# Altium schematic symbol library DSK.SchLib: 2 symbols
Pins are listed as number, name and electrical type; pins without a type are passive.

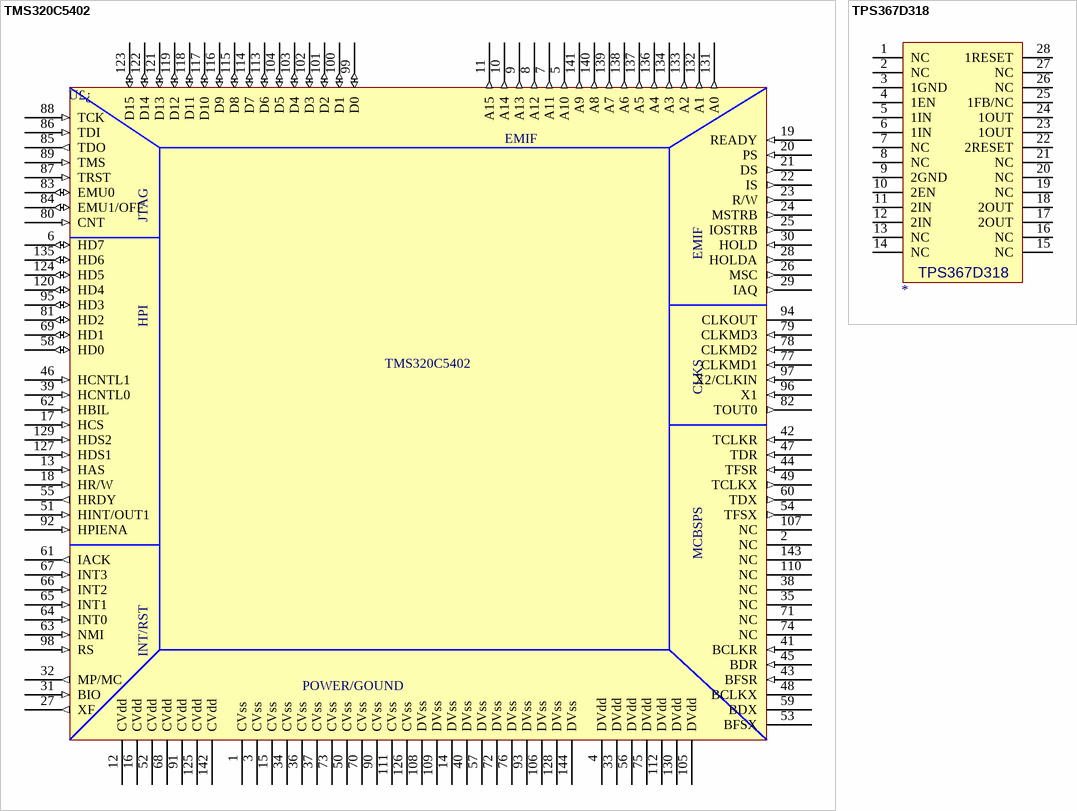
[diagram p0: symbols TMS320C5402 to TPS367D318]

## TMS320C5402
designator U£¿
FIXED-POINT DIGITAL SIGNAL PROCESSORS
pins: 1 CVss (power), 2 NC, 3 CVss (power), 4 DVdd (power), 5 A10 (out), 6 HD7 (io), 7 A11 (out), 8 A12 (out), 9 A13 (out), 10 A14 (out), 11 A15 (out), 12 CVdd (power), 13 HAS (in), 14 DVss (power), 15 CVss (power), 16 CVdd (power), 17 HCS (in), 18 HR/W (in), 19 READY (in), 20 PS (in), 21 DS (out), 22 IS (out), 23 R/W (out), 24 MSTRB (out), 25 IOSTRB (out), 26 MSC (out), 27 XF (out), 28 HOLDA (out), 29 IAQ (out), 30 HOLD (in), 31 BIO (in), 32 MP/MC (out), 33 DVdd (power), 34 CVss (power), 35 NC, 36 CVss (power), 37 CVss (power), 38 NC, 39 HCNTL0 (in), 40 DVss (power), 41 BCLKR (in), 42 TCLKR (in), 43 BFSR (in), 44 TFSR (in), 45 BDR (in), 46 HCNTL1 (in), 47 TDR (in), 48 BCLKX, 49 TCLKX (out), 50 CVss (power), 51 HINT/OUT1 (in), 52 CVdd (power), 53 BFSX, 54 TFSX (out), 55 HRDY (out), 56 DVdd (power), 57 DVss (power), 58 HD0 (io), 59 BDX, 60 TDX (out), 61 IACK (out), 62 HBIL (in), 63 NMI (in), 64 INT0 (in), 65 INT1 (in), 66 INT2 (in), 67 INT3 (in), 68 CVdd (power), 69 HD1 (io), 70 CVss (power), 71 NC, 72 DVss (power), 73 CVss (power), 74 NC, 75 DVdd (power), 76 DVss (power), 77 CLKMD1 (in), 78 CLKMD2 (in), 79 CLKMD3 (in), 80 CNT (in), 81 HD2 (io), 82 TOUT0 (out), 83 EMU0 (io), 84 EMU1/OFF (io), 85 TDO (out), 86 TDI (in), 87 TRST (in), 88 TCK (in), 89 TMS (in), 90 CVss (power), 91 CVdd (power), 92 HPIENA (in), 93 DVss (power), 94 CLKOUT, 95 HD3 (io), 96 X1 (in), 97 X2/CLKIN (in), 98 RS (in), 99 D0 (io), 100 D1 (io), 101 D2 (io), 102 D3 (io), 103 D4 (io), 104 D5 (io), 105 DVdd (power), 106 DVss (power), 107 NC, 108 DVss (power), 109 DVss (power), 110 NC, 111 CVss (power), 112 DVdd (power), 113 D6 (io), 114 D7 (io), 115 D8 (io), 116 D9 (io), 117 D10 (io), 118 D11 (io), 119 D12 (io), 120 HD4 (io), 121 D13 (io), 122 D14 (io), 123 D15 (io), 124 HD5 (io), 125 CVdd (power), 126 CVss (power), 127 HDS1 (in), 128 DVss (power), 129 HDS2 (in), 130 DVdd (power), 131 A0 (out), 132 A1 (out), 133 A2 (out), 134 A3 (out), 135 HD6 (io), 136 A4 (out), 137 A5 (out), 138 A6 (out), 139 A7 (out), 140 A8 (out), 141 A9 (out), 142 CVdd (power), 143 NC, 144 DVss (power)

## TPS367D318
designator *
Manufacturer: Texas Instruments
pins: 1 NC, 2 NC, 3 1GND (power), 4 1EN, 5 1IN, 6 1IN, 7 NC, 8 NC, 9 2GND (power), 10 2EN, 11 2IN, 12 2IN, 13 NC, 14 NC, 15 NC, 16 NC, 17 2OUT, 18 2OUT, 19 NC, 20 NC, 21 NC, 22 2RESET, 23 1OUT, 24 1OUT, 25 1FB/NC, 26 NC, 27 NC, 28 1RESET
